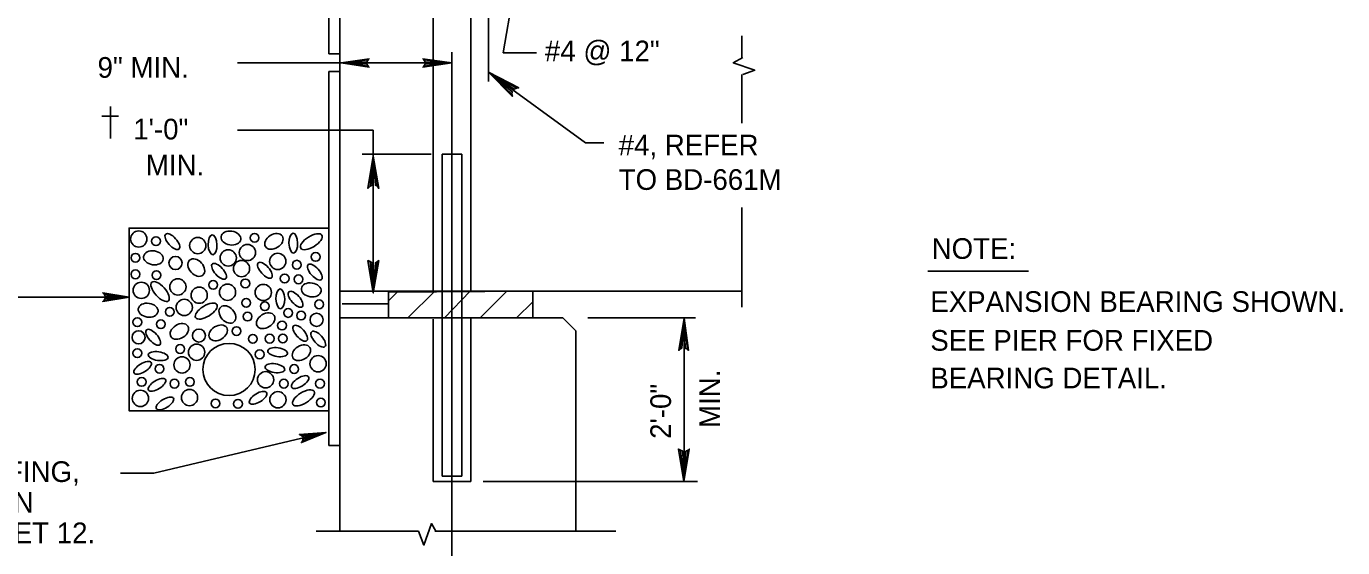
# Model space of a CAD drawing. Extents: x 638653 to 642302, y 298557 to 300414.
# Drawn here: x 640794.5 to 640985.5, y 300141.8 to 300217.4 of the extents above; entities that cross this region are included whole.
import ezdxf

# ---------------------------------------------------------------- set-up
doc = ezdxf.new("R2010")
doc.units = 0
doc.layers.add('1', color=7, linetype='Continuous')

msp = doc.modelspace()

# ---------------------------------------------------------------- linework, layer by layer
at = {"layer": '1'}
for p, q in [((640861.59, 300238.56), (640861.59, 300209.43)), ((640863.71, 300213.59), (640866.88, 300232)), ((640838.42, 300230.16), (640838.42, 300213.44)), ((640840.02, 300228.56), (640840.02, 300144.19)), ((640840.02, 300213.44), (640840.02, 300228.56)), ((640853.55, 300228.56), (640853.55, 300179.03)), ((640859, 300228.56), (640859, 300179.03)), ((640898.31, 300212.94), (640898.31, 300216.07)), ((640838.42, 300213.44), (640840.02, 300213.44)), ((640856.27, 300213.72), (640856.27, 300120.11)), ((640863.71, 300213.59), (640868.52, 300213.59)), ((640825.18, 300212.13), (640856.27, 300212.13)), ((640838.42, 300210.87), (640838.42, 300156.63)), ((640840.02, 300210.87), (640838.42, 300210.87)), ((640840.02, 300156.63), (640840.02, 300210.87)), ((640875.66, 300200.55), (640861.59, 300210.78)), ((640898.31, 300203.4), (640898.31, 300210.44)), ((640806.73, 300201.18), (640806.73, 300205.81)), ((640805.46, 300204.42), (640807.89, 300204.42)), ((640825.18, 300202.4), (640844.86, 300202.4)), ((640844.86, 300179.03), (640844.86, 300202.4)), ((640875.66, 300200.55), (640878.32, 300200.55)), ((640843.22, 300198.88), (640853.24, 300198.88)), ((640854.87, 300152.16), (640854.87, 300198.88)), ((640857.68, 300198.88), (640854.87, 300198.88)), ((640857.68, 300198.88), (640857.68, 300152.16)), ((640898.31, 300176.69), (640898.31, 300191.16)), ((640939.89, 300181.9), (640925.3, 300181.9)), ((640840.02, 300179.03), (640898.31, 300179.03)), ((640867.99, 300179.03), (640847.06, 300178.88)), ((640847.06, 300178.88), (640847.06, 300175.13)), ((640847.06, 300178.88), (640847.06, 300175.13)), ((640867.99, 300175.13), (640867.99, 300179.03)), ((640867.99, 300175.13), (640867.99, 300179.03)), ((640789.33, 300178.14), (640809.44, 300178.14)), ((640840.34, 300177.16), (640847.06, 300177.16)), ((640840.02, 300175.13), (640872.37, 300175.13)), ((640847.06, 300175.13), (640867.99, 300175.13)), ((640853.55, 300174.97), (640853.55, 300151.38)), ((640859, 300151.38), (640859, 300175.13)), ((640872.37, 300175.13), (640874.24, 300173.25)), ((640875.96, 300175.13), (640891.6, 300175.13)), ((640889.95, 300151.67), (640889.95, 300175.11)), ((640874.24, 300144.19), (640874.24, 300173.25)), ((640813.01, 300152.6), (640837.99, 300158.51)), ((640838.42, 300156.63), (640840.02, 300156.63)), ((640808.21, 300152.6), (640813.01, 300152.6)), ((640857.68, 300152.16), (640854.87, 300152.16)), ((640853.55, 300151.38), (640859, 300151.38)), ((640860.81, 300151.38), (640891.89, 300151.38)), ((640836.59, 300144.19), (640851.43, 300144.19)), ((640853.77, 300144.19), (640880.02, 300144.19))]:
    msp.add_line(p, q, dxfattribs=at)
for points in [[(640844.09, 300211.66), (640843.93, 300211.97), (640840.18, 300212.13), (640844.09, 300211.66), (640844.24, 300211.5), (640840.18, 300212.13), (640843.93, 300212.29), (640844.09, 300212.6), (640840.18, 300212.13), (640844.24, 300212.75), (640844.09, 300212.6)], [(640852.21, 300212.6), (640852.37, 300212.29), (640856.27, 300212.13), (640852.21, 300212.6), (640852.06, 300212.75), (640856.27, 300212.13), (640852.37, 300211.97), (640852.21, 300211.66), (640856.27, 300212.13), (640852.06, 300211.5), (640852.21, 300211.66)], [(640898.46, 300210.44), (640900.18, 300211.06), (640897.06, 300212.16), (640898.46, 300212.94)], [(640864.96, 300207.58), (640865.02, 300207.95), (640861.59, 300210.78), (640864.96, 300207.58), (640865.03, 300207.27), (640861.59, 300210.78), (640865.29, 300208.32), (640865.62, 300208.49), (640861.59, 300210.78), (640865.95, 300208.52), (640865.62, 300208.49)], [(640844.39, 300194.23), (640844.7, 300194.39), (640844.86, 300198.61), (640844.39, 300194.23), (640844.07, 300193.92), (640844.86, 300198.61), (640845.17, 300194.39), (640845.48, 300194.23), (640844.86, 300198.61), (640845.64, 300193.92), (640845.48, 300194.23)], [(640845.48, 300183.3), (640845.17, 300183.14), (640844.86, 300178.76), (640845.48, 300183.3), (640845.64, 300183.45), (640844.86, 300178.76), (640844.7, 300183.14), (640844.39, 300183.3), (640844.86, 300178.76), (640844.07, 300183.45), (640844.39, 300183.3)], [(640805.81, 300178.59), (640805.95, 300178.33), (640809.44, 300178.14), (640805.81, 300178.59), (640805.62, 300178.75), (640809.44, 300178.14), (640805.95, 300177.96), (640805.82, 300177.7), (640809.44, 300178.14), (640805.62, 300177.53), (640805.82, 300177.7)], [(640847.06, 300177.63), (640848.46, 300179.03)], [(640849.87, 300175.13), (640853.77, 300179.03)], [(640855.18, 300175.13), (640858.93, 300179.03)], [(640860.34, 300175.13), (640864.24, 300179.03)], [(640865.65, 300175.13), (640867.99, 300177.47)], [(640889.32, 300170.58), (640889.63, 300170.74), (640889.95, 300175.11), (640889.32, 300170.58), (640889.16, 300170.42), (640889.95, 300175.11), (640890.1, 300170.74), (640890.41, 300170.58), (640889.95, 300175.11), (640890.57, 300170.42), (640890.41, 300170.58)], [(640834.35, 300158.12), (640834.55, 300157.9), (640837.99, 300158.51), (640834.35, 300158.12), (640834.14, 300158.23), (640837.99, 300158.51), (640834.63, 300157.54), (640834.57, 300157.26), (640837.99, 300158.51), (640834.42, 300157.04), (640834.57, 300157.26)], [(640890.52, 300155.93), (640890.21, 300155.77), (640889.9, 300151.4), (640890.52, 300155.93), (640890.68, 300156.09), (640889.9, 300151.4), (640889.74, 300155.77), (640889.43, 300155.93), (640889.9, 300151.4), (640889.11, 300156.09), (640889.43, 300155.93)], [(640851.43, 300144.19), (640852.21, 300142.16), (640853.31, 300145.28), (640853.93, 300144.19)]]:
    msp.add_lwpolyline(points, dxfattribs=at)
msp.add_lwpolyline([(640838.42, 300188.17), (640809.44, 300188.17), (640809.44, 300161.65), (640838.42, 300161.65)], close=True, dxfattribs=at)
for centre, radius in [((640810.84, 300186.58), 1.18), ((640813.34, 300186.26), 0.637), ((640819.4, 300185.63), 1.18), ((640827.64, 300186.76), 0.637), ((640810.35, 300183.86), 0.637), ((640823.81, 300183.84), 1.18), ((640826.6, 300184.62), 1.18), ((640831, 300183.33), 1.18), ((640836.5, 300183.98), 0.637), ((640816.17, 300183.1), 0.948), ((640825.74, 300182.29), 1.18), ((640833.75, 300182.85), 0.637), ((640810.35, 300181.46), 0.637), ((640813.4, 300181.34), 0.637), ((640816.51, 300179.63), 1.18), ((640826.29, 300180.14), 0.637), ((640832, 300180.85), 0.637), ((640834, 300180.73), 0.637), ((640811.2, 300179.13), 1.18), ((640819.6, 300178.43), 1.18), ((640821.63, 300179.92), 0.637), ((640823.71, 300178.86), 1.18), ((640828.9, 300178.82), 1.18), ((640817.43, 300176.65), 1.18), ((640826.42, 300177.32), 0.637), ((640829.12, 300176.82), 0.637), ((640837, 300177.1), 0.637), ((640810.63, 300174.52), 0.637), ((640815.33, 300176.02), 0.637), ((640826.62, 300175.32), 0.637), ((640832.5, 300175.85), 0.637), ((640834.38, 300175.47), 0.637), ((640836.63, 300174.85), 0.948), ((640810.81, 300172.31), 0.948), ((640814.04, 300174.21), 0.637), ((640819.57, 300172.57), 0.948), ((640825.02, 300173.22), 0.637), ((640831.62, 300174.02), 0.637), ((640816.83, 300170.62), 0.637), ((640819.23, 300170.15), 1.18), ((640823.93, 300167.65), 3.79), ((640827.38, 300172.09), 0.637), ((640829.82, 300172.12), 0.637), ((640831.73, 300172.15), 0.637), ((640810.63, 300170.02), 0.637), ((640817.11, 300168.31), 1.18), ((640828.38, 300169.84), 0.637), ((640836.85, 300168.48), 1.18), ((640813.84, 300167.75), 0.637), ((640829.23, 300166.15), 1.18), ((640833.38, 300167.71), 0.637), ((640811.26, 300165.84), 0.637), ((640816.01, 300165.59), 0.637), ((640818.26, 300165.84), 0.637), ((640831.88, 300165.59), 0.637), ((640837.13, 300165.59), 0.637), ((640811.08, 300163.45), 1.18), ((640818.2, 300163.57), 1.18), ((640831.02, 300163.25), 1.18), ((640837.25, 300162.84), 0.637), ((640821.96, 300162.72), 0.637), ((640825.23, 300162.66), 0.637)]:
    msp.add_circle(centre, radius, dxfattribs=at)
for centre, major_axis, ratio in [((640815.71, 300186.21), (0.96, -1.08), 0.438009), ((640821.54, 300185.74), (0.04, -1.44), 0.438009), ((640824.2, 300186.72), (1.43, -0.21), 0.696126), ((640830.44, 300186.23), (1.23, 0.76), 0.696126), ((640833.25, 300185.98), (0.04, -1.44), 0.438009), ((640835.87, 300186.19), (1.54, 0.95), 0.438009), ((640812.97, 300183.85), (1.43, -0.21), 0.696126), ((640819.18, 300182.43), (0.96, -1.08), 0.696126), ((640822.48, 300181.89), (0.96, -1.08), 0.438009), ((640829.14, 300182.04), (0.96, -1.08), 0.438009), ((640836.38, 300181.79), (0.96, -1.08), 0.438009), ((640813.93, 300178.96), (1.2, -1.35), 0.438009), ((640831.37, 300177.89), (0.04, -1.44), 0.438009), ((640833.58, 300177.84), (0.96, -1.08), 0.438009), ((640835.85, 300179.2), (1.43, -0.21), 0.696126), ((640812.2, 300176.25), (1.43, -0.21), 0.696126), ((640820.63, 300176.12), (1.54, 0.95), 0.438009), ((640823.69, 300175.63), (0.96, -1.08), 0.696126), ((640829.24, 300174.72), (1.23, 0.76), 0.696126), ((640812.93, 300172.32), (0.96, -1.08), 0.438009), ((640816.73, 300173.17), (1.23, 0.76), 0.696126), ((640822.36, 300172.96), (1.23, 0.76), 0.696126), ((640834.26, 300172.91), (0.96, -1.08), 0.438009), ((640836.88, 300172.04), (0.96, -1.08), 0.438009), ((640834.43, 300170.08), (1.23, 0.76), 0.696126), ((640813.65, 300169.59), (1.43, -0.21), 0.438009), ((640830.98, 300170.16), (1.43, -0.21), 0.438009), ((640811.4, 300167.88), (1.23, 0.76), 0.438009), ((640830.58, 300167.84), (1.43, -0.21), 0.438009), ((640813.48, 300165.42), (1.23, 0.76), 0.438009), ((640834.24, 300165.82), (1.23, 0.76), 0.438009), ((640814.63, 300162.71), (1.23, 0.76), 0.438009), ((640828.14, 300163.54), (1.23, 0.76), 0.438009), ((640834.73, 300163.53), (1.54, 0.95), 0.438009)]:
    msp.add_ellipse(centre, major_axis=major_axis, ratio=ratio, dxfattribs=at)

# ---------------------------------------------------------------- texts
for s, p in [('#4 @ 12"', (640869.75, 300212.37)), ('9" MIN.', (640804.86, 300209.98)), ('#4, REFER', (640880.45, 300198.71)), ('TO BD-661M', (640880.45, 300193.71)), ('NOTE:', (640925.85, 300183.7)), ('EXPANSION BEARING SHOWN.', (640925.65, 300176)), ('SEE PIER FOR FIXED', (640925.65, 300170.37)), ('BEARING DETAIL.', (640925.65, 300164.91)), ('WATERPROOFING,', (640765.28, 300151.32)), ('SEE DETAIL ON', (640765.28, 300146.88)), ('BC-788M, SHEET 12.', (640765.28, 300142.44))]:
    msp.add_text(s, height=3, dxfattribs=at).set_placement(p)
for s, rotation, p in [('1\'-0"', 360, (640810.04, 300201.03)), ('MIN.', 360, (640811.87, 300195.8)), ('MIN.', 90, (640895.13, 300159.16)), ('2\'-0"', 90, (640888.04, 300157.58))]:
    msp.add_text(s, height=3, rotation=rotation, dxfattribs=at).set_placement(p)

doc.saveas('drawing.dxf')
